(* Logix 5000 project; controller Test vendor 1 type 14 code 92 rev 33.11; software revision 33.00; part 2 of 3 *)
(* tags used below, declared in another part *)
   K50ProTouch : Banner_K50ProTouch_v2;
   Port_Data : Banner_IOL_Port_v4;
   Port : DINT;
   Local_Control : DINT;
   Command_Being_Processed : BOOL;
   Update_Archive : BOOL;
   Index_Write_Control : DINT;
   Index_Write_Inprocess : INT;
   Inprocess_Index : DINT;
   SP_Index : DINT;   // State Parameters Index
   SP_Write_Index : DINT;
   SP_W_Index : DINT;
(* Banner_K50ProTouch_Param_v4, continued *)

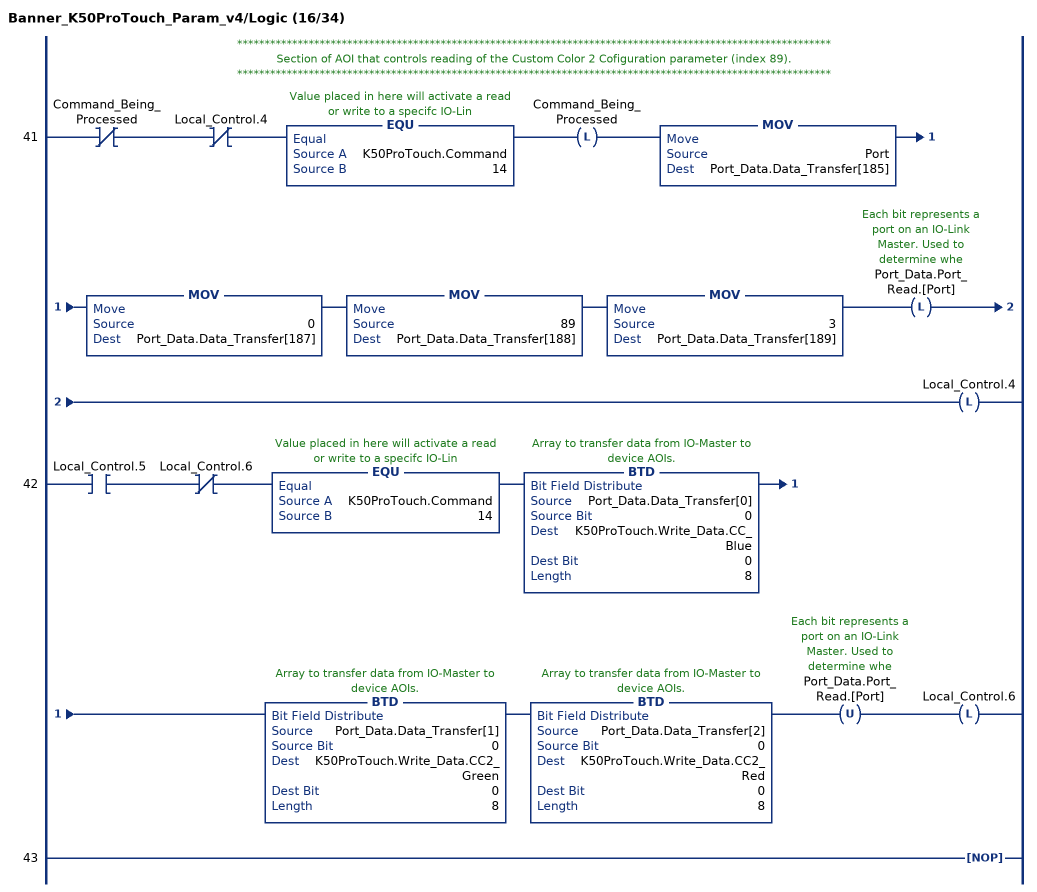
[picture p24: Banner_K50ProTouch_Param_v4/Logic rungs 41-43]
   // ************************************************************************************************************
   // Section of AOI that controls reading of the Custom Color 2 Cofiguration parameter (index 89).
   // ************************************************************************************************************
   41: XIO(Command_Being_Processed)XIO(Local_Control.4)EQU(K50ProTouch.Command,14)OTL(Command_Being_Processed)MOV(Port,Port_Data.Data_Transfer[185])MOV(0,Port_Data.Data_Transfer[187])MOV(89,Port_Data.Data_Transfer[188])MOV(3,Port_Data.Data_Transfer[189])OTL(Port_Data.Port_Read.[Port])OTL(Local_Control.4);
   42: XIC(Local_Control.5)XIO(Local_Control.6)EQU(K50ProTouch.Command,14)BTD(Port_Data.Data_Transfer[0],0,K50ProTouch.Write_Data.CC_Blue,0,8)BTD(Port_Data.Data_Transfer[1],0,K50ProTouch.Write_Data.CC2_Green,0,8)BTD(Port_Data.Data_Transfer[2],0,K50ProTouch.Write_Data.CC2_Red,0,8)OTU(Port_Data.Port_Read.[Port])OTL(Local_Control.6);
   43: NOP();
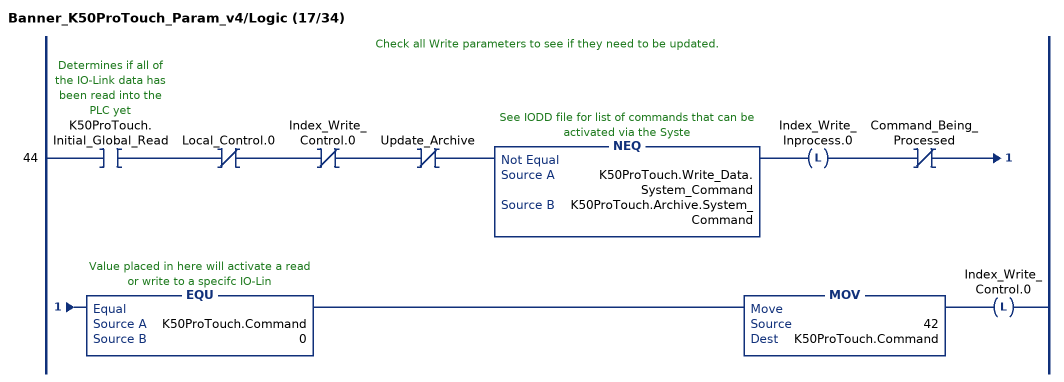
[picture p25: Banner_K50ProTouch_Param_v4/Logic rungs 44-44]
   // Check all Write parameters to see if they need to be updated.
   44: XIC(K50ProTouch.Initial_Global_Read)XIO(Local_Control.0)XIO(Index_Write_Control.0)XIO(Update_Archive)NEQ(K50ProTouch.Write_Data.System_Command,K50ProTouch.Archive.System_Command)OTL(Index_Write_Inprocess.0)XIO(Command_Being_Processed)EQU(K50ProTouch.Command,0)MOV(42,K50ProTouch.Command)OTL(Index_Write_Control.0);
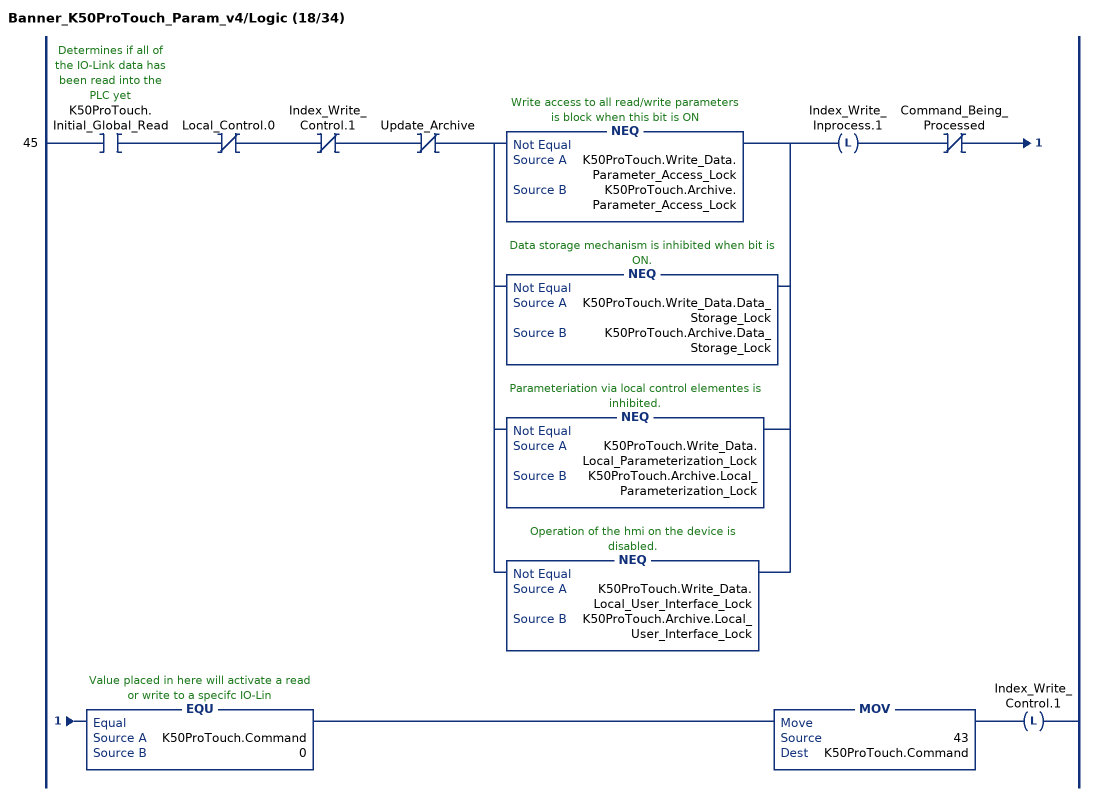
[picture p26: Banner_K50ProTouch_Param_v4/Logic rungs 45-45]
   45: XIC(K50ProTouch.Initial_Global_Read)XIO(Local_Control.0)XIO(Index_Write_Control.1)XIO(Update_Archive)[NEQ(K50ProTouch.Write_Data.Parameter_Access_Lock,K50ProTouch.Archive.Parameter_Access_Lock) ,NEQ(K50ProTouch.Write_Data.Data_Storage_Lock,K50ProTouch.Archive.Data_Storage_Lock) ,NEQ(K50ProTouch.Write_Data.Local_Parameterization_Lock,K50ProTouch.Archive.Local_Parameterization_Lock) ,NEQ(K50ProTouch.Write_Data.Local_User_Interface_Lock,K50ProTouch.Archive.Local_User_Interface_Lock) ]OTL(Index_Write_Inprocess.1)XIO(Command_Being_Processed)EQU(K50ProTouch.Command,0)MOV(43,K50ProTouch.Command)OTL(Index_Write_Control.1);
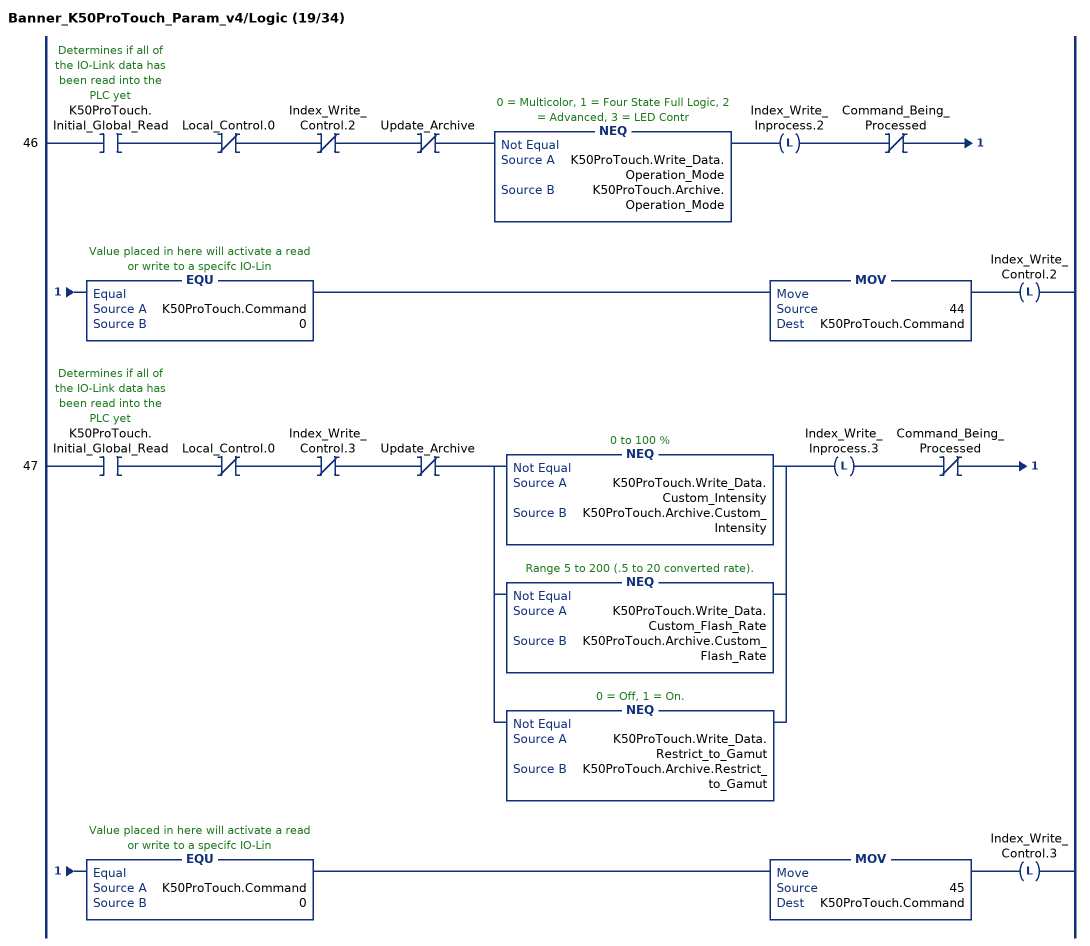
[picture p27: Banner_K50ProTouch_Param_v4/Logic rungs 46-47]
   46: XIC(K50ProTouch.Initial_Global_Read)XIO(Local_Control.0)XIO(Index_Write_Control.2)XIO(Update_Archive)NEQ(K50ProTouch.Write_Data.Operation_Mode,K50ProTouch.Archive.Operation_Mode)OTL(Index_Write_Inprocess.2)XIO(Command_Being_Processed)EQU(K50ProTouch.Command,0)MOV(44,K50ProTouch.Command)OTL(Index_Write_Control.2);
   47: XIC(K50ProTouch.Initial_Global_Read)XIO(Local_Control.0)XIO(Index_Write_Control.3)XIO(Update_Archive)[NEQ(K50ProTouch.Write_Data.Custom_Intensity,K50ProTouch.Archive.Custom_Intensity) ,NEQ(K50ProTouch.Write_Data.Custom_Flash_Rate,K50ProTouch.Archive.Custom_Flash_Rate) ,NEQ(K50ProTouch.Write_Data.Restrict_to_Gamut,K50ProTouch.Archive.Restrict_to_Gamut) ]OTL(Index_Write_Inprocess.3)XIO(Command_Being_Processed)EQU(K50ProTouch.Command,0)MOV(45,K50ProTouch.Command)OTL(Index_Write_Control.3);
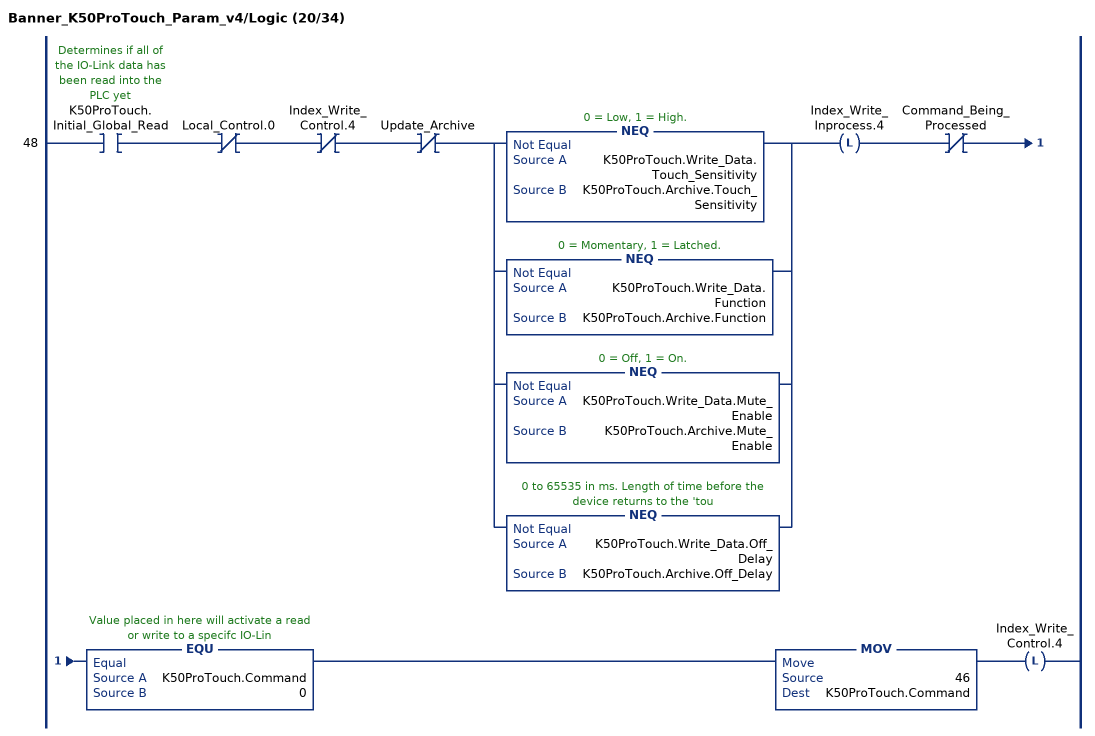
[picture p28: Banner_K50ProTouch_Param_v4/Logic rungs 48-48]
   48: XIC(K50ProTouch.Initial_Global_Read)XIO(Local_Control.0)XIO(Index_Write_Control.4)XIO(Update_Archive)[NEQ(K50ProTouch.Write_Data.Touch_Sensitivity,K50ProTouch.Archive.Touch_Sensitivity) ,NEQ(K50ProTouch.Write_Data.Function,K50ProTouch.Archive.Function) ,NEQ(K50ProTouch.Write_Data.Mute_Enable,K50ProTouch.Archive.Mute_Enable) ,NEQ(K50ProTouch.Write_Data.Off_Delay,K50ProTouch.Archive.Off_Delay) ]OTL(Index_Write_Inprocess.4)XIO(Command_Being_Processed)EQU(K50ProTouch.Command,0)MOV(46,K50ProTouch.Command)OTL(Index_Write_Control.4);
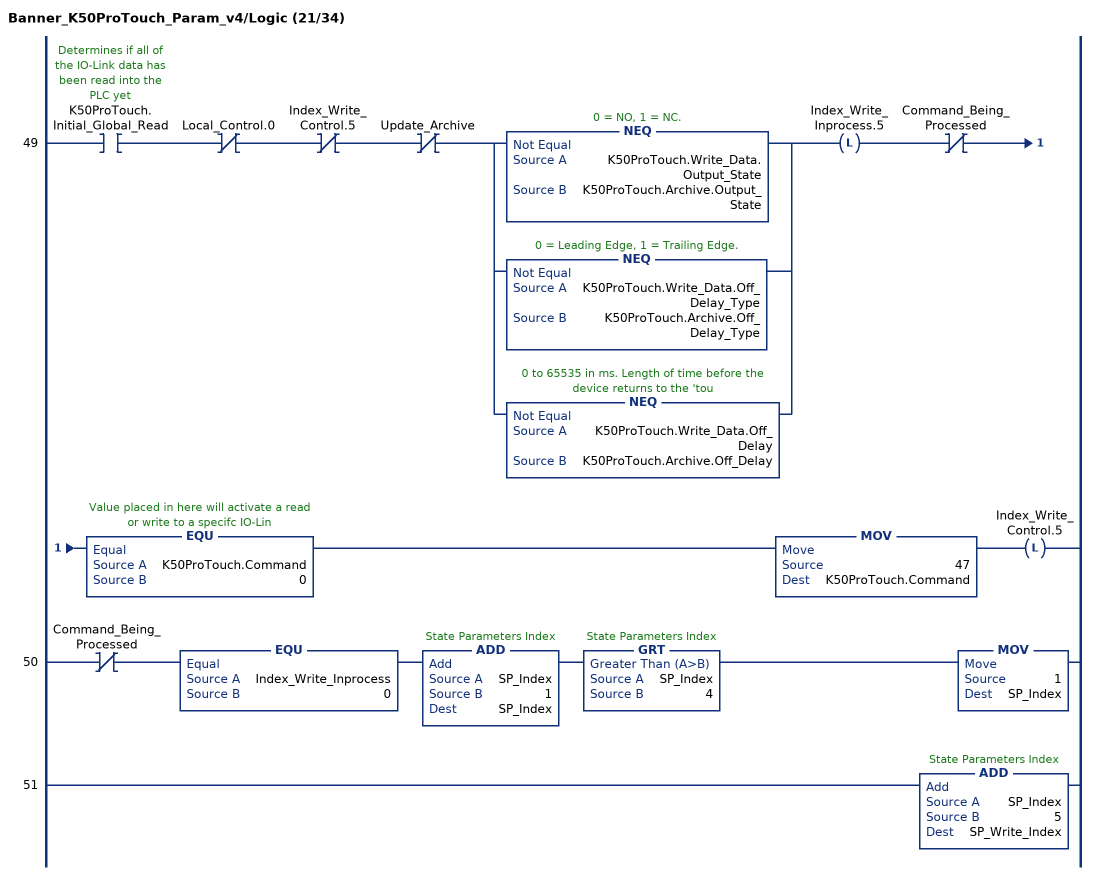
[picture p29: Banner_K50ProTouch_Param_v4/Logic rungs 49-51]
   49: XIC(K50ProTouch.Initial_Global_Read)XIO(Local_Control.0)XIO(Index_Write_Control.5)XIO(Update_Archive)[NEQ(K50ProTouch.Write_Data.Output_State,K50ProTouch.Archive.Output_State) ,NEQ(K50ProTouch.Write_Data.Off_Delay_Type,K50ProTouch.Archive.Off_Delay_Type) ,NEQ(K50ProTouch.Write_Data.Off_Delay,K50ProTouch.Archive.Off_Delay) ]OTL(Index_Write_Inprocess.5)XIO(Command_Being_Processed)EQU(K50ProTouch.Command,0)MOV(47,K50ProTouch.Command)OTL(Index_Write_Control.5);
   50: XIO(Command_Being_Processed)EQU(Index_Write_Inprocess,0)ADD(SP_Index,1,SP_Index)GRT(SP_Index,4)MOV(1,SP_Index);
   51: ADD(SP_Index,5,SP_Write_Index);
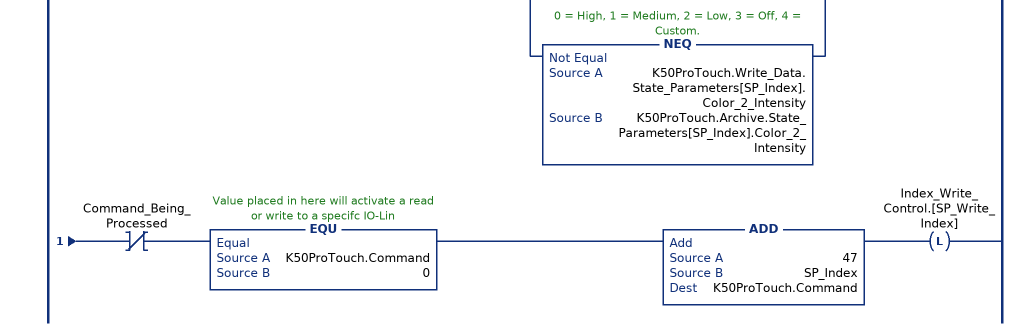
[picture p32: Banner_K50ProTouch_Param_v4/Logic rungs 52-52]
   52: XIC(K50ProTouch.Initial_Global_Read)XIO(Local_Control.0)XIO(Index_Write_Control.[SP_Write_Index])XIO(Update_Archive)[NEQ(K50ProTouch.Write_Data.State_Parameters[SP_Index].Type,K50ProTouch.Archive.State_Parameters[SP_Index].Type) ,NEQ(K50ProTouch.Write_Data.State_Parameters[SP_Index].Direction,K50ProTouch.Archive.State_Parameters[SP_Index].Direction) ,NEQ(K50ProTouch.Write_Data.State_Parameters[SP_Index].Pattern,K50ProTouch.Archive.State_Parameters[SP_Index].Pattern) ,NEQ(K50ProTouch.Write_Data.State_Parameters[SP_Index].Speed,K50ProTouch.Archive.State_Parameters[SP_Index].Speed) ,NEQ(K50ProTouch.Write_Data.State_Parameters[SP_Index].Vibration_Feedback,K50ProTouch.Archive.State_Parameters[SP_Index].Vibration_Feedback) ,NEQ(K50ProTouch.Write_Data.State_Parameters[SP_Index].Off_Delay_Type,K50ProTouch.Archive.State_Parameters[SP_Index].Off_Delay_Type) ,NEQ(K50ProTouch.Write_Data.State_Parameters[SP_Index].Off_Delay,K50ProTouch.Archive.State_Parameters[SP_Index].Off_Delay) ,NEQ(K50ProTouch.Write_Data.State_Parameters[SP_Index].Static_Sequence,K50ProTouch.Archive.State_Parameters[SP_Index].Static_Sequence) ,NEQ(K50ProTouch.Write_Data.State_Parameters[SP_Index].Sequence_Start_Location,K50ProTouch.Archive.State_Parameters[SP_Index].Sequence_Start_Location) ,NEQ(K50ProTouch.Write_Data.State_Parameters[SP_Index].Color_1,K50ProTouch.Archive.State_Parameters[SP_Index].Color_1) ,NEQ(K50ProTouch.Write_Data.State_Parameters[SP_Index].Color_1_Intensity,K50ProTouch.Archive.State_Parameters[SP_Index].Color_1_Intensity) ,NEQ(K50ProTouch.Write_Data.State_Parameters[SP_Index].Color_2,K50ProTouch.Archive.State_Parameters[SP_Index].Color_2) ,NEQ(K50ProTouch.Write_Data.State_Parameters[SP_Index].Color_2_Intensity,K50ProTouch.Archive.State_Parameters[SP_Index].Color_2_Intensity) ]OTL(Index_Write_Inprocess.[SP_Write_Index])XIO(Command_Being_Processed)EQU(K50ProTouch.Command,0)ADD(47,SP_Index,K50ProTouch.Command)OTL(Index_Write_Control.[SP_Write_Index]);
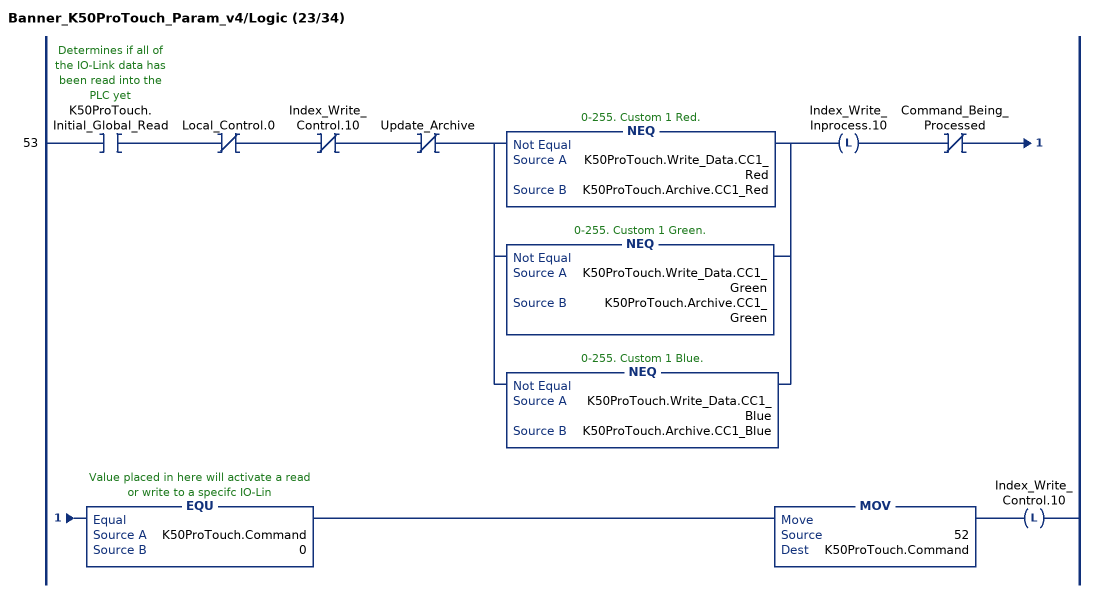
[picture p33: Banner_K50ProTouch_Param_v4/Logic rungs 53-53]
   53: XIC(K50ProTouch.Initial_Global_Read)XIO(Local_Control.0)XIO(Index_Write_Control.10)XIO(Update_Archive)[NEQ(K50ProTouch.Write_Data.CC1_Red,K50ProTouch.Archive.CC1_Red) ,NEQ(K50ProTouch.Write_Data.CC1_Green,K50ProTouch.Archive.CC1_Green) ,NEQ(K50ProTouch.Write_Data.CC1_Blue,K50ProTouch.Archive.CC1_Blue) ]OTL(Index_Write_Inprocess.10)XIO(Command_Being_Processed)EQU(K50ProTouch.Command,0)MOV(52,K50ProTouch.Command)OTL(Index_Write_Control.10);
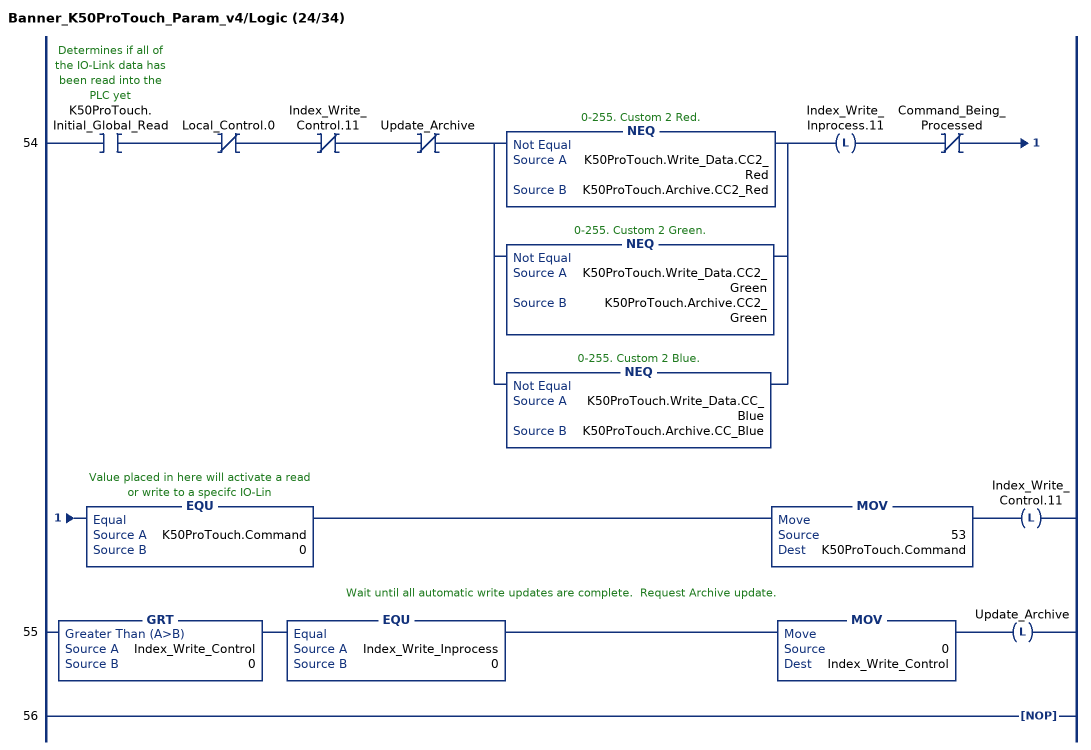
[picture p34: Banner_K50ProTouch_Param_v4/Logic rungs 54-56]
   54: XIC(K50ProTouch.Initial_Global_Read)XIO(Local_Control.0)XIO(Index_Write_Control.11)XIO(Update_Archive)[NEQ(K50ProTouch.Write_Data.CC2_Red,K50ProTouch.Archive.CC2_Red) ,NEQ(K50ProTouch.Write_Data.CC2_Green,K50ProTouch.Archive.CC2_Green) ,NEQ(K50ProTouch.Write_Data.CC_Blue,K50ProTouch.Archive.CC_Blue) ]OTL(Index_Write_Inprocess.11)XIO(Command_Being_Processed)EQU(K50ProTouch.Command,0)MOV(53,K50ProTouch.Command)OTL(Index_Write_Control.11);
   // Wait until all automatic write updates are complete.  Request Archive update.
   55: GRT(Index_Write_Control,0)EQU(Index_Write_Inprocess,0)MOV(0,Index_Write_Control)OTL(Update_Archive);
   56: NOP();
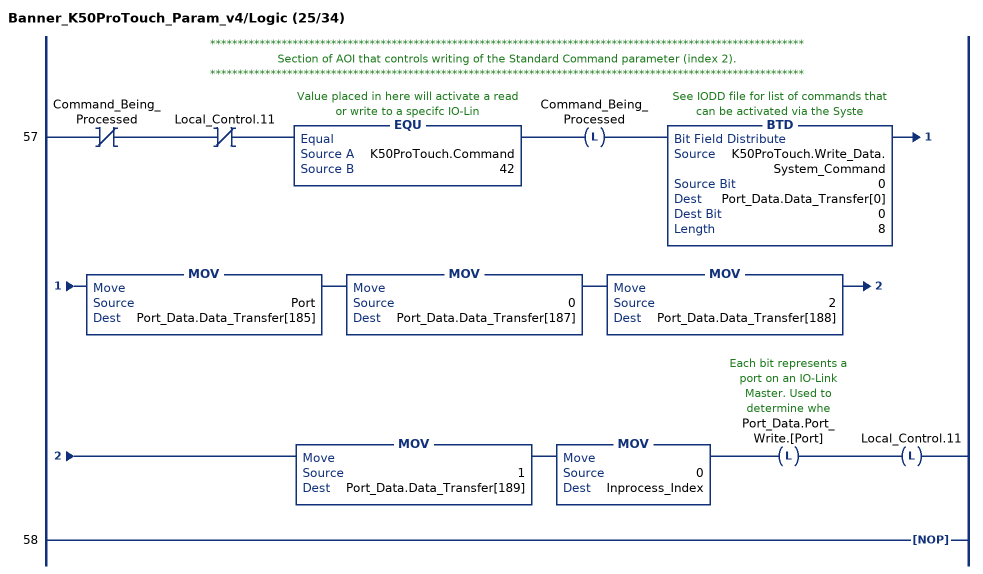
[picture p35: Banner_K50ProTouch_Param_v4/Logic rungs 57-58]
   // ************************************************************************************************************
   // Section of AOI that controls writing of the Standard Command parameter (index 2).
   // ************************************************************************************************************
   57: XIO(Command_Being_Processed)XIO(Local_Control.11)EQU(K50ProTouch.Command,42)OTL(Command_Being_Processed)BTD(K50ProTouch.Write_Data.System_Command,0,Port_Data.Data_Transfer[0],0,8)MOV(Port,Port_Data.Data_Transfer[185])MOV(0,Port_Data.Data_Transfer[187])MOV(2,Port_Data.Data_Transfer[188])MOV(1,Port_Data.Data_Transfer[189])MOV(0,Inprocess_Index)OTL(Port_Data.Port_Write.[Port])OTL(Local_Control.11);
   58: NOP();
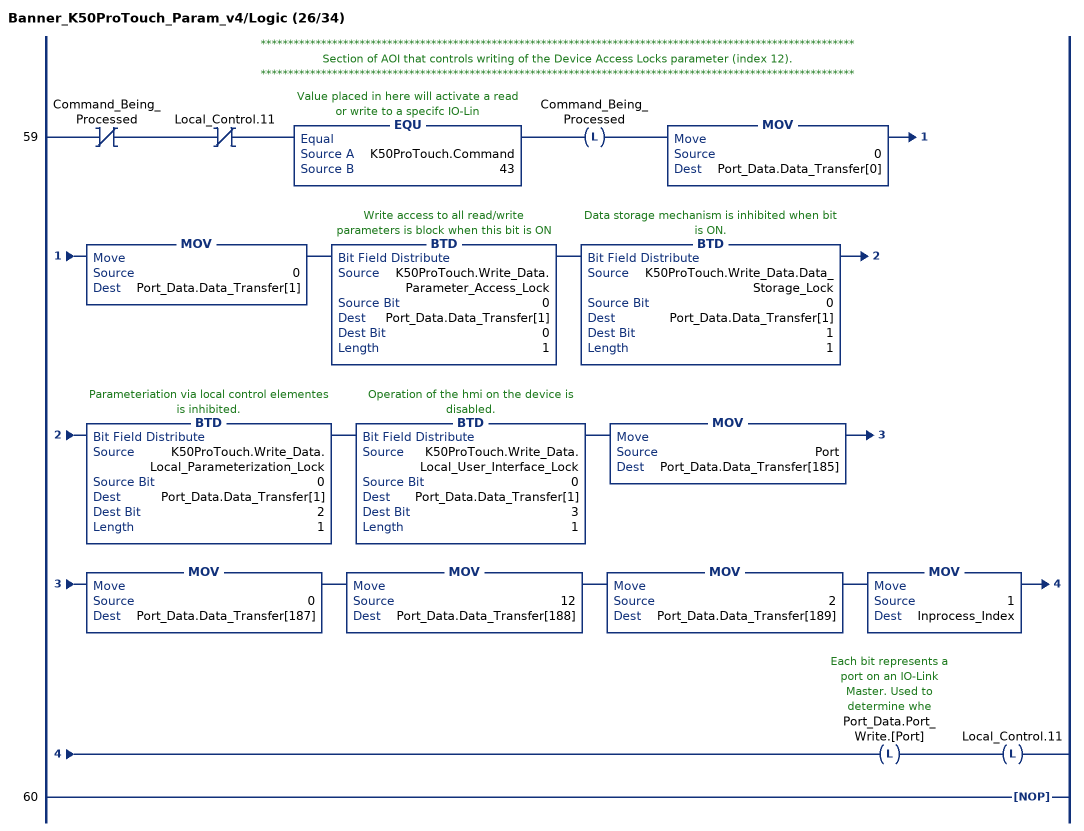
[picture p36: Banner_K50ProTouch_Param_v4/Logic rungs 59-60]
   // ************************************************************************************************************
   // Section of AOI that controls writing of the Device Access Locks parameter (index 12).
   // ************************************************************************************************************
   59: XIO(Command_Being_Processed)XIO(Local_Control.11)EQU(K50ProTouch.Command,43)OTL(Command_Being_Processed)MOV(0,Port_Data.Data_Transfer[0])MOV(0,Port_Data.Data_Transfer[1])BTD(K50ProTouch.Write_Data.Parameter_Access_Lock,0,Port_Data.Data_Transfer[1],0,1)BTD(K50ProTouch.Write_Data.Data_Storage_Lock,0,Port_Data.Data_Transfer[1],1,1)BTD(K50ProTouch.Write_Data.Local_Parameterization_Lock,0,Port_Data.Data_Transfer[1],2,1)BTD(K50ProTouch.Write_Data.Local_User_Interface_Lock,0,Port_Data.Data_Transfer[1],3,1)MOV(Port,Port_Data.Data_Transfer[185])MOV(0,Port_Data.Data_Transfer[187])MOV(12,Port_Data.Data_Transfer[188])MOV(2,Port_Data.Data_Transfer[189])MOV(1,Inprocess_Index)OTL(Port_Data.Port_Write.[Port])OTL(Local_Control.11);
   60: NOP();
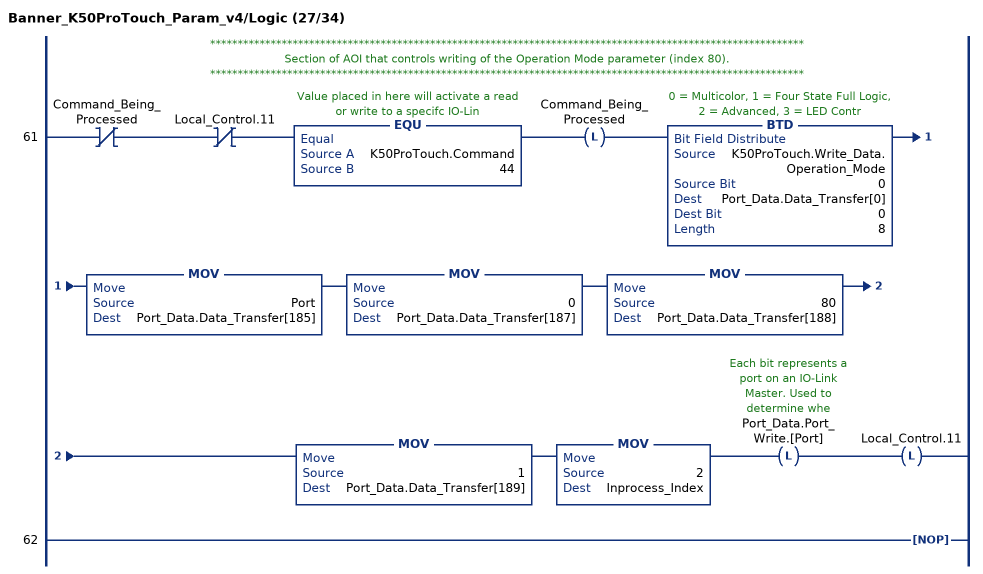
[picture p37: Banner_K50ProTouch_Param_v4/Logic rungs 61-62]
   // ************************************************************************************************************
   // Section of AOI that controls writing of the Operation Mode parameter (index 80).
   // ************************************************************************************************************
   61: XIO(Command_Being_Processed)XIO(Local_Control.11)EQU(K50ProTouch.Command,44)OTL(Command_Being_Processed)BTD(K50ProTouch.Write_Data.Operation_Mode,0,Port_Data.Data_Transfer[0],0,8)MOV(Port,Port_Data.Data_Transfer[185])MOV(0,Port_Data.Data_Transfer[187])MOV(80,Port_Data.Data_Transfer[188])MOV(1,Port_Data.Data_Transfer[189])MOV(2,Inprocess_Index)OTL(Port_Data.Port_Write.[Port])OTL(Local_Control.11);
   62: NOP();
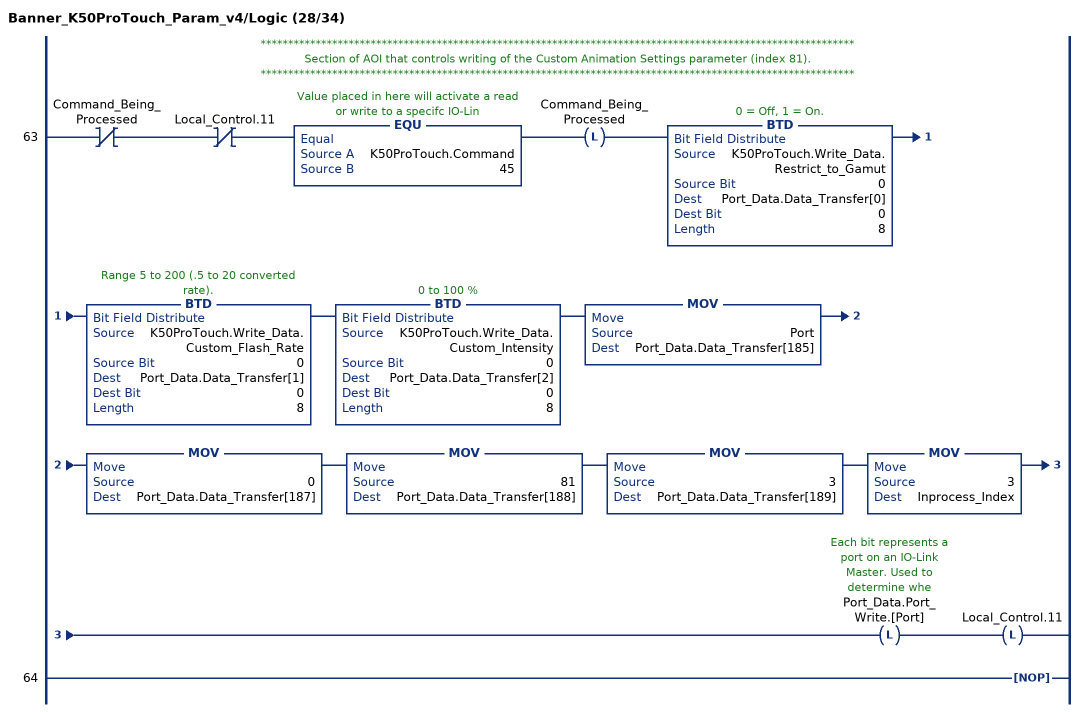
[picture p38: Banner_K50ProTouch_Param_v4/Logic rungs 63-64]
   // ************************************************************************************************************
   // Section of AOI that controls writing of the Custom Animation Settings parameter (index 81).
   // ************************************************************************************************************
   63: XIO(Command_Being_Processed)XIO(Local_Control.11)EQU(K50ProTouch.Command,45)OTL(Command_Being_Processed)BTD(K50ProTouch.Write_Data.Restrict_to_Gamut,0,Port_Data.Data_Transfer[0],0,8)BTD(K50ProTouch.Write_Data.Custom_Flash_Rate,0,Port_Data.Data_Transfer[1],0,8)BTD(K50ProTouch.Write_Data.Custom_Intensity,0,Port_Data.Data_Transfer[2],0,8)MOV(Port,Port_Data.Data_Transfer[185])MOV(0,Port_Data.Data_Transfer[187])MOV(81,Port_Data.Data_Transfer[188])MOV(3,Port_Data.Data_Transfer[189])MOV(3,Inprocess_Index)OTL(Port_Data.Port_Write.[Port])OTL(Local_Control.11);
   64: NOP();
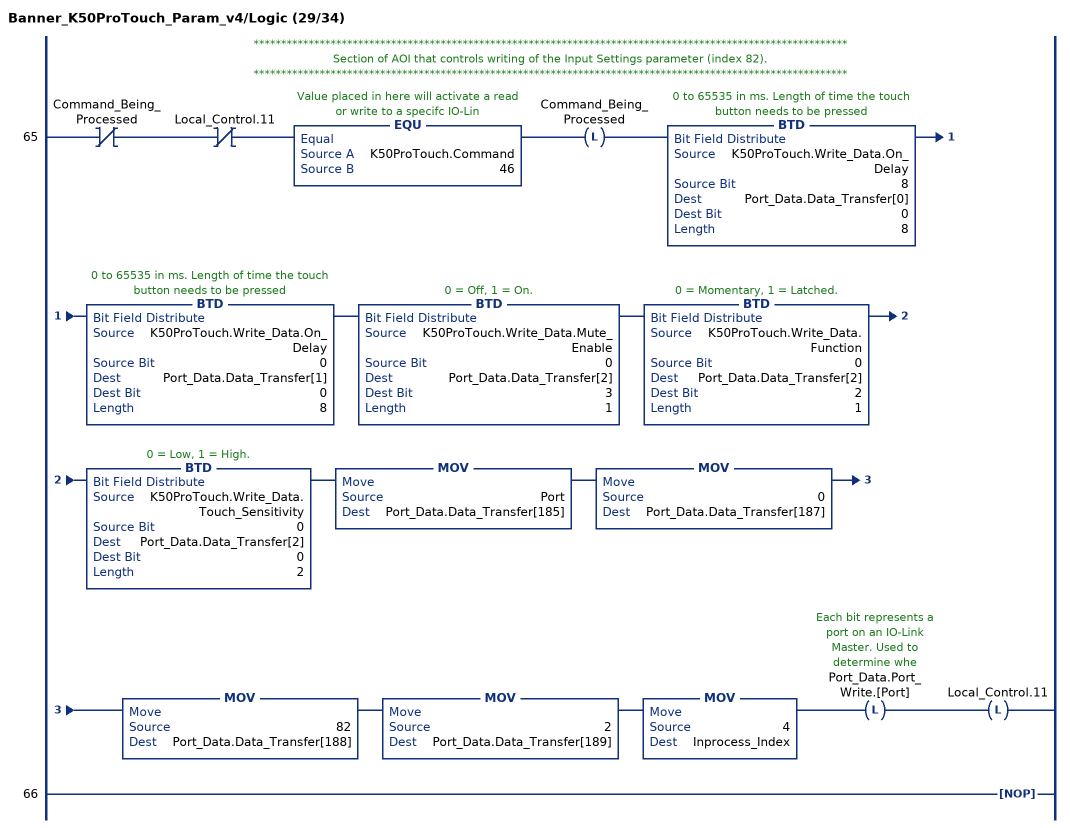
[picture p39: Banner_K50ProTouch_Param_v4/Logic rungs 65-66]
   // ************************************************************************************************************
   // Section of AOI that controls writing of the Input Settings parameter (index 82).
   // ************************************************************************************************************
   65: XIO(Command_Being_Processed)XIO(Local_Control.11)EQU(K50ProTouch.Command,46)OTL(Command_Being_Processed)BTD(K50ProTouch.Write_Data.On_Delay,8,Port_Data.Data_Transfer[0],0,8)BTD(K50ProTouch.Write_Data.On_Delay,0,Port_Data.Data_Transfer[1],0,8)BTD(K50ProTouch.Write_Data.Mute_Enable,0,Port_Data.Data_Transfer[2],3,1)BTD(K50ProTouch.Write_Data.Function,0,Port_Data.Data_Transfer[2],2,1)BTD(K50ProTouch.Write_Data.Touch_Sensitivity,0,Port_Data.Data_Transfer[2],0,2)MOV(Port,Port_Data.Data_Transfer[185])MOV(0,Port_Data.Data_Transfer[187])MOV(82,Port_Data.Data_Transfer[188])MOV(2,Port_Data.Data_Transfer[189])MOV(4,Inprocess_Index)OTL(Port_Data.Port_Write.[Port])OTL(Local_Control.11);
   66: NOP();
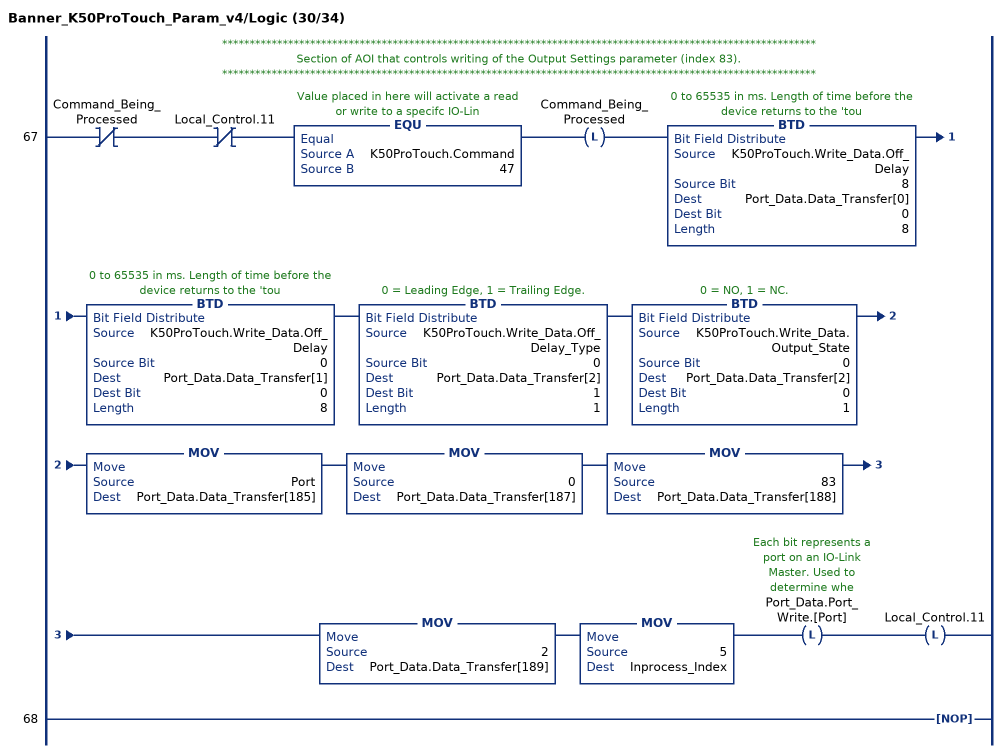
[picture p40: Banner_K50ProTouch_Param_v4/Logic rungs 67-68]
   // ************************************************************************************************************
   // Section of AOI that controls writing of the Output Settings parameter (index 83).
   // ************************************************************************************************************
   67: XIO(Command_Being_Processed)XIO(Local_Control.11)EQU(K50ProTouch.Command,47)OTL(Command_Being_Processed)BTD(K50ProTouch.Write_Data.Off_Delay,8,Port_Data.Data_Transfer[0],0,8)BTD(K50ProTouch.Write_Data.Off_Delay,0,Port_Data.Data_Transfer[1],0,8)BTD(K50ProTouch.Write_Data.Off_Delay_Type,0,Port_Data.Data_Transfer[2],1,1)BTD(K50ProTouch.Write_Data.Output_State,0,Port_Data.Data_Transfer[2],0,1)MOV(Port,Port_Data.Data_Transfer[185])MOV(0,Port_Data.Data_Transfer[187])MOV(83,Port_Data.Data_Transfer[188])MOV(2,Port_Data.Data_Transfer[189])MOV(5,Inprocess_Index)OTL(Port_Data.Port_Write.[Port])OTL(Local_Control.11);
   68: NOP();
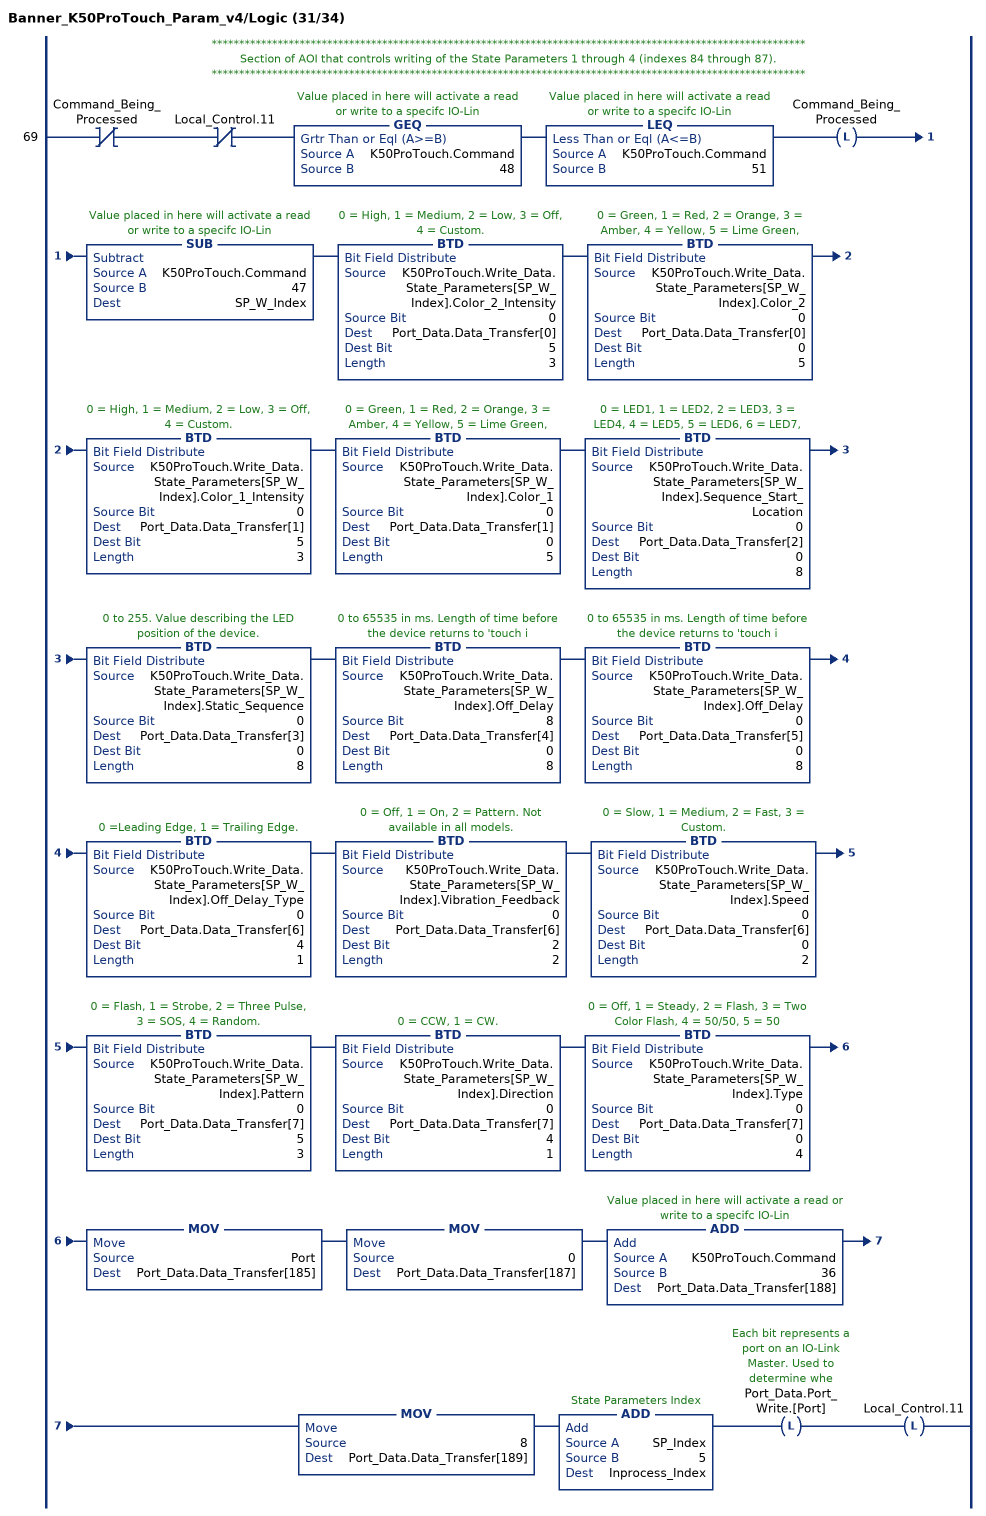
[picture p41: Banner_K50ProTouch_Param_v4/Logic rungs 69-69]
   // ************************************************************************************************************
   // Section of AOI that controls writing of the State Parameters 1 through 4 (indexes 84 through 87).
   // ************************************************************************************************************
   69: XIO(Command_Being_Processed)XIO(Local_Control.11)GEQ(K50ProTouch.Command,48)LEQ(K50ProTouch.Command,51)OTL(Command_Being_Processed)SUB(K50ProTouch.Command,47,SP_W_Index)BTD(K50ProTouch.Write_Data.State_Parameters[SP_W_Index].Color_2_Intensity,0,Port_Data.Data_Transfer[0],5,3)BTD(K50ProTouch.Write_Data.State_Parameters[SP_W_Index].Color_2,0,Port_Data.Data_Transfer[0],0,5)BTD(K50ProTouch.Write_Data.State_Parameters[SP_W_Index].Color_1_Intensity,0,Port_Data.Data_Transfer[1],5,3)BTD(K50ProTouch.Write_Data.State_Parameters[SP_W_Index].Color_1,0,Port_Data.Data_Transfer[1],0,5)BTD(K50ProTouch.Write_Data.State_Parameters[SP_W_Index].Sequence_Start_Location,0,Port_Data.Data_Transfer[2],0,8)BTD(K50ProTouch.Write_Data.State_Parameters[SP_W_Index].Static_Sequence,0,Port_Data.Data_Transfer[3],0,8)BTD(K50ProTouch.Write_Data.State_Parameters[SP_W_Index].Off_Delay,8,Port_Data.Data_Transfer[4],0,8)BTD(K50ProTouch.Write_Data.State_Parameters[SP_W_Index].Off_Delay,0,Port_Data.Data_Transfer[5],0,8)BTD(K50ProTouch.Write_Data.State_Parameters[SP_W_Index].Off_Delay_Type,0,Port_Data.Data_Transfer[6],4,1)BTD(K50ProTouch.Write_Data.State_Parameters[SP_W_Index].Vibration_Feedback,0,Port_Data.Data_Transfer[6],2,2)BTD(K50ProTouch.Write_Data.State_Parameters[SP_W_Index].Speed,0,Port_Data.Data_Transfer[6],0,2)BTD(K50ProTouch.Write_Data.State_Parameters[SP_W_Index].Pattern,0,Port_Data.Data_Transfer[7],5,3)BTD(K50ProTouch.Write_Data.State_Parameters[SP_W_Index].Direction,0,Port_Data.Data_Transfer[7],4,1)BTD(K50ProTouch.Write_Data.State_Parameters[SP_W_Index].Type,0,Port_Data.Data_Transfer[7],0,4)MOV(Port,Port_Data.Data_Transfer[185])MOV(0,Port_Data.Data_Transfer[187])ADD(K50ProTouch.Command,36,Port_Data.Data_Transfer[188])MOV(8,Port_Data.Data_Transfer[189])ADD(SP_Index,5,Inprocess_Index)OTL(Port_Data.Port_Write.[Port])OTL(Local_Control.11);
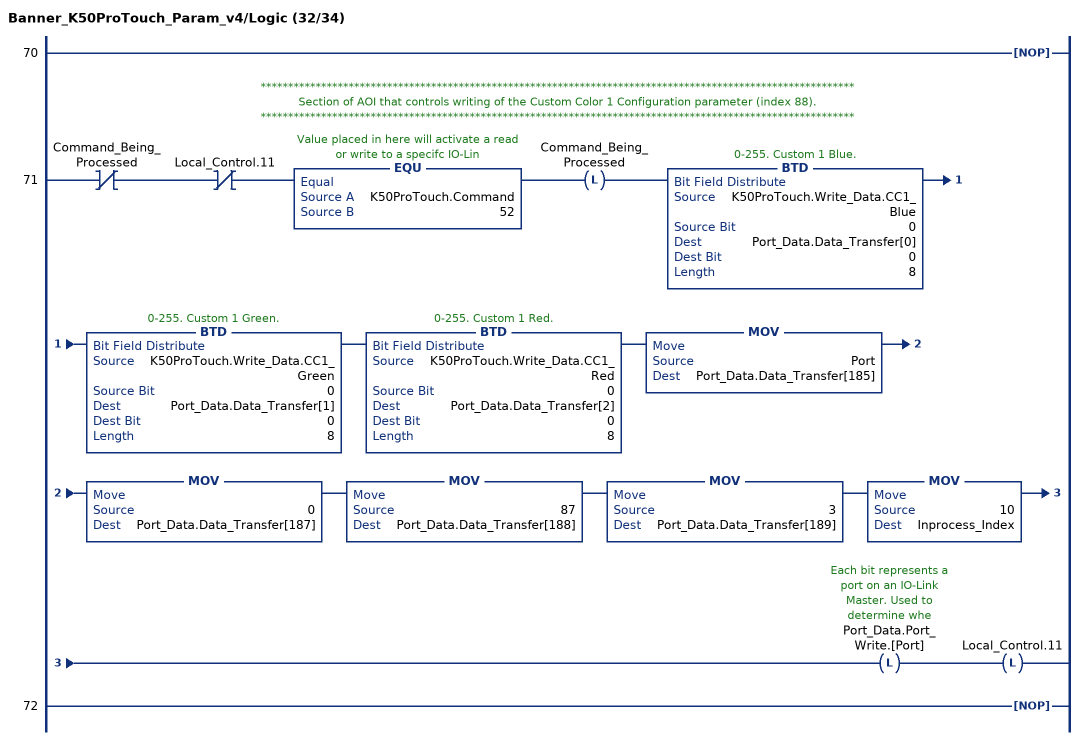
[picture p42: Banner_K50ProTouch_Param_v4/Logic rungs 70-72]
   70: NOP();
   // ************************************************************************************************************
   // Section of AOI that controls writing of the Custom Color 1 Configuration parameter (index 88).
   // ************************************************************************************************************
   71: XIO(Command_Being_Processed)XIO(Local_Control.11)EQU(K50ProTouch.Command,52)OTL(Command_Being_Processed)BTD(K50ProTouch.Write_Data.CC1_Blue,0,Port_Data.Data_Transfer[0],0,8)BTD(K50ProTouch.Write_Data.CC1_Green,0,Port_Data.Data_Transfer[1],0,8)BTD(K50ProTouch.Write_Data.CC1_Red,0,Port_Data.Data_Transfer[2],0,8)MOV(Port,Port_Data.Data_Transfer[185])MOV(0,Port_Data.Data_Transfer[187])MOV(87,Port_Data.Data_Transfer[188])MOV(3,Port_Data.Data_Transfer[189])MOV(10,Inprocess_Index)OTL(Port_Data.Port_Write.[Port])OTL(Local_Control.11);
   72: NOP();
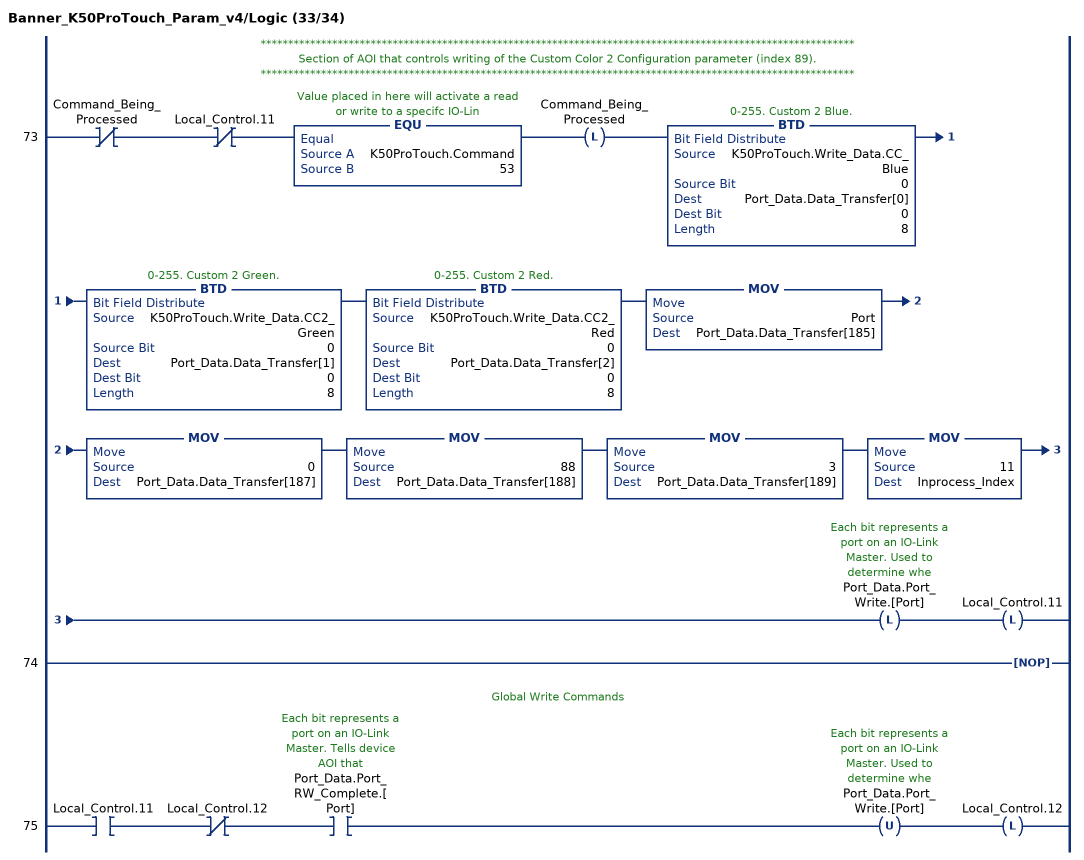
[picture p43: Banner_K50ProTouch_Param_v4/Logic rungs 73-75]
   // ************************************************************************************************************
   // Section of AOI that controls writing of the Custom Color 2 Configuration parameter (index 89).
   // ************************************************************************************************************
   73: XIO(Command_Being_Processed)XIO(Local_Control.11)EQU(K50ProTouch.Command,53)OTL(Command_Being_Processed)BTD(K50ProTouch.Write_Data.CC_Blue,0,Port_Data.Data_Transfer[0],0,8)BTD(K50ProTouch.Write_Data.CC2_Green,0,Port_Data.Data_Transfer[1],0,8)BTD(K50ProTouch.Write_Data.CC2_Red,0,Port_Data.Data_Transfer[2],0,8)MOV(Port,Port_Data.Data_Transfer[185])MOV(0,Port_Data.Data_Transfer[187])MOV(88,Port_Data.Data_Transfer[188])MOV(3,Port_Data.Data_Transfer[189])MOV(11,Inprocess_Index)OTL(Port_Data.Port_Write.[Port])OTL(Local_Control.11);
   74: NOP();
   // Global Write Commands
   75: XIC(Local_Control.11)XIO(Local_Control.12)XIC(Port_Data.Port_RW_Complete.[Port])OTU(Port_Data.Port_Write.[Port])OTL(Local_Control.12);
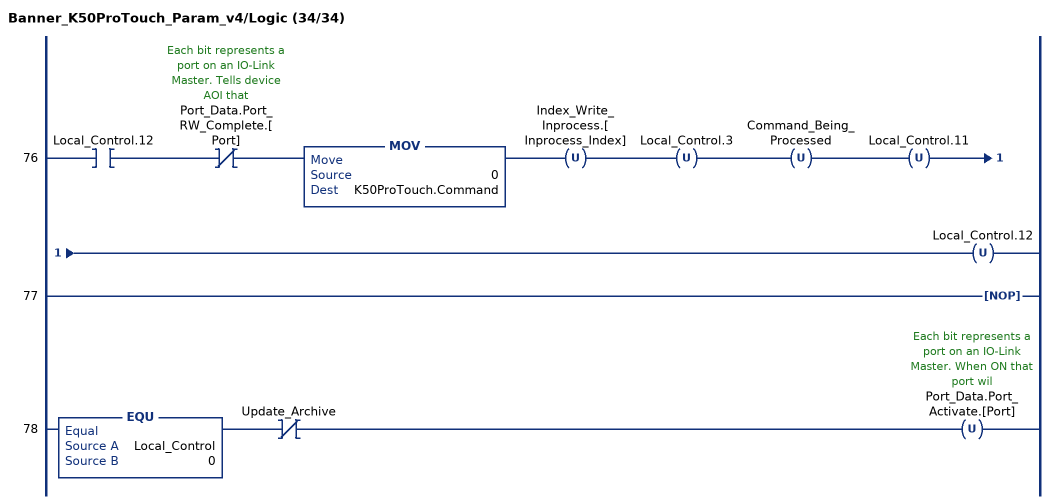
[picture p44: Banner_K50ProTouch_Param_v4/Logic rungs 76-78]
   76: XIC(Local_Control.12)XIO(Port_Data.Port_RW_Complete.[Port])MOV(0,K50ProTouch.Command)OTU(Index_Write_Inprocess.[Inprocess_Index])OTU(Local_Control.3)OTU(Command_Being_Processed)OTU(Local_Control.11)OTU(Local_Control.12);
   77: NOP();
   78: EQU(Local_Control,0)XIO(Update_Archive)OTU(Port_Data.Port_Activate.[Port]);
END_ROUTINE
END_ADD_ON_INSTRUCTION
